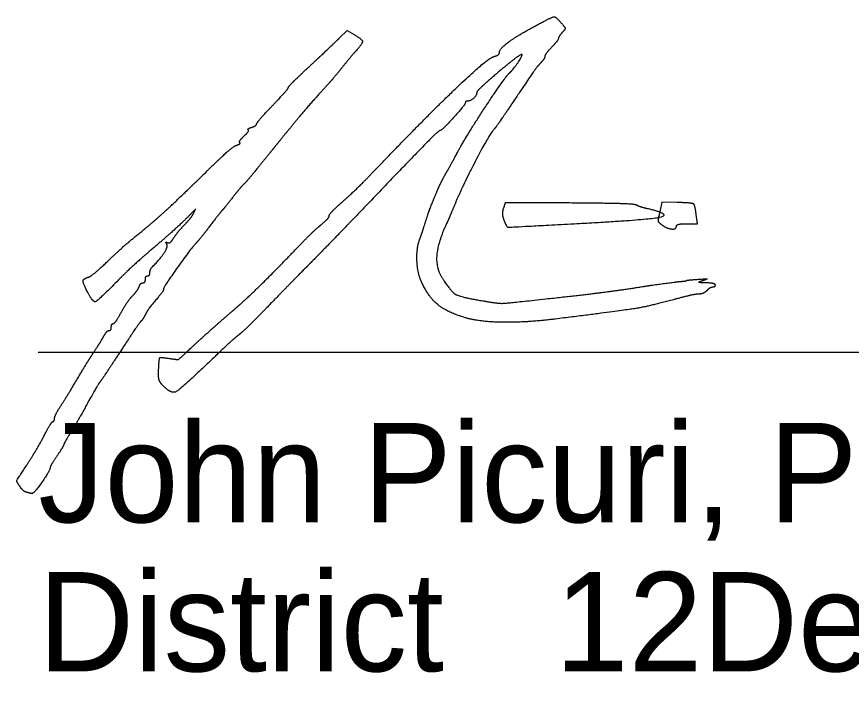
# Model space of a CAD drawing. Extents: x 0 to 81.5, y 0 to 35.2.
# Drawn here: x 24.497 to 25.674, y 8.063 to 9.028 of the extents above; entities that cross this region are included whole.
import ezdxf

# ---------------------------------------------------------------- set-up
doc = ezdxf.new("R2010")
doc.units = 0
doc.layers.add('SH_Data', color=7, linetype='Continuous')
doc.layers.add('SH_Text', color=7, linetype='Continuous')

msp = doc.modelspace()

# ---------------------------------------------------------------- linework, layer by layer
at = {"layer": 'SH_Data'}
msp.add_line((24.5279, 8.555), (28.0279, 8.555), dxfattribs=at)
msp.add_line((24.5279, 8.555), (28.0279, 8.555), dxfattribs=at)
at = {"layer": 'SH_Text'}
for p, q in [((25.1843, 8.7411), (25.1843, 8.7411)), ((25.4072, 8.7342), (25.4072, 8.7342)), ((24.7028, 8.5086), (24.7028, 8.5086)), ((24.5119, 8.3571), (24.5119, 8.3571))]:
    msp.add_line(p, q, dxfattribs=at)
for points in [[(24.9527, 8.9976), (24.9635, 9.0082), (24.9732, 9.0025)], [(24.7467, 8.7502), (24.7501, 8.7566), (24.7437, 8.7502)], [(25.277, 8.765), (25.1863, 8.7654), (25.1837, 8.7575)], [(25.4288, 8.7657), (25.407, 8.7662), (25.4041, 8.7525)], [(25.4425, 8.7358), (25.4573, 8.7358), (25.4556, 8.7489)]]:
    msp.add_lwpolyline(points, dxfattribs=at)
for points in [[(25.2302, 9.0154), (25.2528, 9.0275), (25.2579, 9.0276), (25.2676, 9.0159)], [(25.1781, 8.9771), (25.1781, 8.9823), (25.2041, 9.0014), (25.2302, 9.0154)], [(25.2676, 9.0159), (25.271, 9.0117), (25.2709, 9.0099), (25.2665, 9.0051)], [(24.9732, 9.0025), (24.9847, 8.9957), (24.9854, 8.9897), (24.9756, 8.979)], [(25.2665, 9.0051), (25.2636, 9.0019), (25.2613, 8.9982), (25.2613, 8.997)], [(24.9112, 8.9584), (24.9281, 8.9741), (24.9468, 8.9918), (24.9527, 8.9976)], [(25.2613, 8.997), (25.2613, 8.9957), (25.257, 8.99), (25.2517, 8.9844)], [(24.9756, 8.979), (24.9716, 8.9746), (24.9626, 8.9638), (24.9556, 8.9551)], [(25.2517, 8.9844), (25.2464, 8.9788), (25.2421, 8.973), (25.2421, 8.9716)], [(24.9988, 8.8073), (25.0691, 8.8809), (25.1611, 8.969), (25.1699, 8.9712)], [(25.2101, 8.974), (25.2101, 8.9762), (25.185, 8.9568), (25.1615, 8.9364)], [(25.1699, 8.9712), (25.1744, 8.9724), (25.1781, 8.975), (25.1781, 8.9771)], [(25.1926, 8.9486), (25.1972, 8.9526), (25.2101, 8.9713), (25.2101, 8.974)], [(25.2421, 8.9716), (25.2421, 8.9701), (25.2403, 8.9669), (25.2381, 8.9645)], [(24.8805, 8.9277), (24.8805, 8.9289), (24.8943, 8.9427), (24.9112, 8.9584)], [(25.2381, 8.9645), (25.23, 8.9554), (25.2268, 8.951), (25.2004, 8.9118)], [(24.9556, 8.9551), (24.9486, 8.9464), (24.9407, 8.9369), (24.9381, 8.9341)], [(25.1188, 8.836), (25.1307, 8.8584), (25.1861, 8.9428), (25.1926, 8.9486)], [(24.9381, 8.9341), (24.9267, 8.922), (24.8959, 8.8867), (24.8852, 8.8734)], [(25.1615, 8.9364), (25.1531, 8.929), (25.1461, 8.9218), (25.1461, 8.9204)], [(24.8581, 8.9022), (24.8704, 8.9151), (24.8805, 8.9266), (24.8805, 8.9277)], [(25.1461, 8.9204), (25.146, 8.9166), (25.1375, 8.9086), (25.1335, 8.9086)], [(25.1335, 8.9086), (25.1316, 8.9086), (25.13, 8.9075), (25.13, 8.9062)], [(25.2004, 8.9118), (25.1855, 8.8898), (25.1727, 8.8711), (25.1717, 8.8702)], [(24.8357, 8.8763), (24.8357, 8.8776), (24.8457, 8.8893), (24.8581, 8.9022)], [(25.13, 8.9062), (25.1298, 8.9033), (25.0968, 8.867), (25.0943, 8.867)], [(24.829, 8.8717), (24.8327, 8.8729), (24.8357, 8.8749), (24.8357, 8.8763)], [(24.8852, 8.8734), (24.8787, 8.8655), (24.8688, 8.8532), (24.863, 8.8462)], [(24.8179, 8.8591), (24.8222, 8.8631), (24.8249, 8.8671), (24.824, 8.868)], [(24.824, 8.868), (24.8231, 8.8689), (24.8254, 8.8706), (24.829, 8.8717)], [(25.0943, 8.867), (25.0923, 8.867), (25.0616, 8.8358), (24.9919, 8.7632)], [(25.1717, 8.8702), (25.1649, 8.8637), (25.1253, 8.7878), (25.1125, 8.7566)], [(24.8073, 8.8463), (24.8108, 8.8475), (24.8129, 8.8492), (24.812, 8.8502)], [(24.812, 8.8502), (24.811, 8.8511), (24.8137, 8.8552), (24.8179, 8.8591)], [(24.7708, 8.8148), (24.7873, 8.831), (24.8038, 8.8452), (24.8073, 8.8463)], [(24.863, 8.8462), (24.8573, 8.8391), (24.8456, 8.8247), (24.8371, 8.8142)], [(25.1042, 8.8094), (25.1058, 8.812), (25.1124, 8.824), (25.1188, 8.836)], [(24.6782, 8.7287), (24.6956, 8.7429), (24.7296, 8.7745), (24.7708, 8.8148)], [(24.8371, 8.8142), (24.8286, 8.8036), (24.82, 8.7935), (24.818, 8.7918)], [(24.958, 8.7678), (24.9689, 8.7775), (24.9873, 8.7952), (24.9988, 8.8073)], [(25.0741, 8.739), (25.079, 8.7553), (25.0974, 8.7984), (25.1042, 8.8094)], [(24.818, 8.7918), (24.816, 8.79), (24.8087, 8.7814), (24.8018, 8.7726)], [(24.8018, 8.7726), (24.7949, 8.7638), (24.7885, 8.7559), (24.7875, 8.755)], [(24.9381, 8.747), (24.9381, 8.7488), (24.947, 8.7582), (24.958, 8.7678)], [(24.9919, 8.7632), (24.9667, 8.7368), (24.9309, 8.7), (24.9125, 8.6813)], [(25.1125, 8.7566), (25.1096, 8.7495), (25.1059, 8.7409), (25.1042, 8.7374)], [(25.1837, 8.7575), (25.1822, 8.7529), (25.1824, 8.746), (25.1843, 8.7411)], [(25.3713, 8.7621), (25.3693, 8.7634), (25.3269, 8.7647), (25.277, 8.765)], [(25.2837, 8.7358), (25.3852, 8.7412), (25.4222, 8.7486), (25.3884, 8.7566)], [(25.3884, 8.7566), (25.381, 8.7583), (25.3732, 8.7608), (25.3713, 8.7621)], [(25.4522, 8.7635), (25.4513, 8.7644), (25.4408, 8.7654), (25.4288, 8.7657)], [(25.4556, 8.7489), (25.4546, 8.756), (25.4531, 8.7626), (25.4522, 8.7635)], [(24.7437, 8.7502), (24.7319, 8.7382), (24.7093, 8.7179), (24.6853, 8.6974)], [(24.734, 8.7342), (24.7392, 8.7395), (24.7449, 8.7467), (24.7467, 8.7502)], [(24.7875, 8.755), (24.7866, 8.7541), (24.779, 8.7445), (24.7707, 8.7336)], [(24.9264, 8.7342), (24.9328, 8.7394), (24.9381, 8.7452), (24.9381, 8.747)], [(25.4041, 8.7525), (25.4015, 8.7407), (25.402, 8.7382), (25.4072, 8.7342)], [(24.719, 8.7158), (24.7221, 8.7206), (24.7289, 8.7289), (24.734, 8.7342)], [(24.7707, 8.7336), (24.7624, 8.7227), (24.7537, 8.7119), (24.7514, 8.7096)], [(24.8968, 8.7058), (24.9066, 8.7161), (24.92, 8.7289), (24.9264, 8.7342)], [(25.0658, 8.714), (25.0674, 8.7181), (25.0711, 8.7293), (25.0741, 8.739)], [(25.1042, 8.7374), (25.0914, 8.7099), (25.0882, 8.6739), (25.0972, 8.6597)], [(25.1843, 8.7411), (25.1881, 8.731), (25.1912, 8.7308), (25.2837, 8.7358)], [(25.4072, 8.7342), (25.4142, 8.7289), (25.4277, 8.7278), (25.4277, 8.7326)], [(25.4277, 8.7326), (25.4277, 8.7343), (25.4343, 8.7358), (25.4425, 8.7358)], [(24.6251, 8.6822), (24.6465, 8.7025), (24.6521, 8.7074), (24.6782, 8.7287)], [(24.7514, 8.7096), (24.7447, 8.7029), (24.7045, 8.6465), (24.7045, 8.6438)], [(24.709, 8.7073), (24.7076, 8.7096), (24.708, 8.7103), (24.71, 8.7091)], [(24.71, 8.7091), (24.7119, 8.708), (24.7159, 8.711), (24.719, 8.7158)], [(25.0676, 8.6554), (25.0623, 8.6674), (25.0613, 8.7027), (25.0658, 8.714)], [(24.6853, 8.6974), (24.6721, 8.6862), (24.6532, 8.6689), (24.6434, 8.6589)], [(24.6894, 8.6756), (24.701, 8.6875), (24.7112, 8.7039), (24.709, 8.7073)], [(24.8125, 8.6222), (24.8252, 8.6333), (24.8708, 8.6785), (24.8968, 8.7058)], [(24.5983, 8.6604), (24.6015, 8.6614), (24.6136, 8.6712), (24.6251, 8.6822)], [(24.6853, 8.6668), (24.6853, 8.6693), (24.6871, 8.6732), (24.6894, 8.6756)], [(24.9125, 8.6813), (24.894, 8.6626), (24.8656, 8.6335), (24.8493, 8.6167)], [(24.6789, 8.6574), (24.6789, 8.66), (24.6803, 8.6622), (24.6821, 8.6622)], [(24.6821, 8.6622), (24.6838, 8.6622), (24.6853, 8.6642), (24.6853, 8.6668)], [(24.5973, 8.6396), (24.5909, 8.6521), (24.5912, 8.6582), (24.5983, 8.6604)], [(24.6434, 8.6589), (24.6123, 8.6275), (24.6051, 8.6245), (24.5973, 8.6396)], [(24.6703, 8.6474), (24.6714, 8.6503), (24.6737, 8.6526), (24.6756, 8.6526)], [(24.6756, 8.6526), (24.6774, 8.6526), (24.6789, 8.6547), (24.6789, 8.6574)], [(25.1298, 8.6033), (25.1041, 8.6109), (25.0771, 8.6335), (25.0676, 8.6554)], [(25.0972, 8.6597), (25.11, 8.6397), (25.1233, 8.6323), (25.1559, 8.6269)], [(25.3813, 8.6474), (25.3941, 8.6494), (25.4241, 8.6535), (25.4341, 8.6545)], [(25.4341, 8.6545), (25.4385, 8.6549), (25.4421, 8.6555), (25.4421, 8.6558)], [(25.4421, 8.6558), (25.4421, 8.6561), (25.4493, 8.6568), (25.4581, 8.6575)], [(25.4581, 8.6575), (25.4698, 8.6583), (25.4719, 8.6579), (25.4661, 8.6559)], [(25.4661, 8.6559), (25.4588, 8.6535), (25.4592, 8.6532), (25.4701, 8.6529)], [(25.4701, 8.6529), (25.4767, 8.6527), (25.4821, 8.6511), (25.4821, 8.6494)], [(25.4821, 8.6494), (25.4821, 8.6476), (25.4805, 8.6462), (25.4786, 8.6462)], [(24.6607, 8.634), (24.6649, 8.6386), (24.6692, 8.6446), (24.6703, 8.6474)], [(24.7045, 8.6438), (24.7045, 8.6417), (24.7011, 8.6372), (24.6858, 8.6188)], [(25.2437, 8.6299), (25.2997, 8.636), (25.3497, 8.6424), (25.3813, 8.6474)], [(25.4704, 8.6414), (25.4678, 8.6387), (25.4625, 8.6366), (25.4586, 8.6365)], [(25.4786, 8.6462), (25.4767, 8.6462), (25.473, 8.644), (25.4704, 8.6414)], [(24.6446, 8.6104), (24.6492, 8.6188), (24.6564, 8.6295), (24.6607, 8.634)], [(25.1559, 8.6269), (25.1766, 8.6234), (25.188, 8.6238), (25.2437, 8.6299)], [(25.4277, 8.6299), (25.39, 8.6196), (25.3508, 8.6131), (25.2565, 8.6014)], [(25.4586, 8.6365), (25.4548, 8.6365), (25.4409, 8.6335), (25.4277, 8.6299)], [(24.6858, 8.6188), (24.6842, 8.6169), (24.6811, 8.6119), (24.6788, 8.6076)], [(24.7826, 8.5962), (24.793, 8.6052), (24.8065, 8.6169), (24.8125, 8.6222)], [(24.8493, 8.6167), (24.833, 8.5999), (24.8153, 8.5828), (24.81, 8.5786)], [(24.6336, 8.595), (24.635, 8.595), (24.64, 8.6019), (24.6446, 8.6104)], [(24.6788, 8.6076), (24.6766, 8.6033), (24.6737, 8.5991), (24.6726, 8.5982)], [(25.2565, 8.6014), (25.2157, 8.5964), (25.1501, 8.5974), (25.1298, 8.6033)], [(24.6309, 8.5902), (24.6309, 8.5928), (24.6321, 8.595), (24.6336, 8.595)], [(24.6726, 8.5982), (24.6714, 8.5973), (24.6586, 8.5786), (24.6442, 8.5566)], [(24.7445, 8.5619), (24.755, 8.5717), (24.7722, 8.5871), (24.7826, 8.5962)], [(24.6206, 8.5778), (24.6229, 8.582), (24.6262, 8.5854), (24.6278, 8.5854)], [(24.6278, 8.5854), (24.6295, 8.5854), (24.6309, 8.5875), (24.6309, 8.5902)], [(24.6082, 8.5578), (24.6128, 8.5647), (24.6183, 8.5737), (24.6206, 8.5778)], [(24.81, 8.5786), (24.8046, 8.5744), (24.7898, 8.561), (24.7771, 8.5488)], [(24.5762, 8.5057), (24.5933, 8.5344), (24.601, 8.5469), (24.6082, 8.5578)], [(24.6442, 8.5566), (24.6297, 8.5346), (24.6167, 8.5151), (24.6152, 8.5132)], [(24.7137, 8.5458), (24.7244, 8.5441), (24.7268, 8.5453), (24.7445, 8.5619)], [(24.6975, 8.5281), (24.6982, 8.5459), (24.7002, 8.548), (24.7137, 8.5458)], [(24.7771, 8.5488), (24.7295, 8.5031), (24.715, 8.4952), (24.7028, 8.5086)], [(24.7028, 8.5086), (24.699, 8.5129), (24.6972, 8.5194), (24.6975, 8.5281)], [(24.6152, 8.5132), (24.6127, 8.51), (24.6084, 8.5026), (24.5872, 8.4646)], [(24.5613, 8.4818), (24.567, 8.4907), (24.5737, 8.5014), (24.5762, 8.5057)], [(24.5509, 8.4617), (24.5509, 8.4638), (24.5555, 8.4728), (24.5613, 8.4818)], [(24.5483, 8.4569), (24.5497, 8.4574), (24.5509, 8.4596), (24.5509, 8.4617)], [(24.5872, 8.4646), (24.5825, 8.4562), (24.5753, 8.444), (24.5712, 8.4375)], [(24.5359, 8.4366), (24.5413, 8.4471), (24.5469, 8.4563), (24.5483, 8.4569)], [(24.5114, 8.3953), (24.5194, 8.4075), (24.5304, 8.426), (24.5359, 8.4366)], [(24.5712, 8.4375), (24.567, 8.4309), (24.5637, 8.4248), (24.5637, 8.424)], [(24.5637, 8.424), (24.5637, 8.4232), (24.5593, 8.4161), (24.5541, 8.4083)], [(24.5541, 8.4083), (24.5488, 8.4005), (24.5445, 8.3929), (24.5445, 8.3916)], [(24.5017, 8.3659), (24.4972, 8.3728), (24.4978, 8.3746), (24.5114, 8.3953)], [(24.5445, 8.3916), (24.5445, 8.3879), (24.5214, 8.3549), (24.5191, 8.3554)], [(24.5119, 8.3571), (24.509, 8.3579), (24.5044, 8.3619), (24.5017, 8.3659)], [(24.5191, 8.3554), (24.5181, 8.3556), (24.5149, 8.3564), (24.5119, 8.3571)]]:
    msp.add_open_spline(points, degree=2, dxfattribs=at)

# ---------------------------------------------------------------- texts
for s, p in [('John Picuri, P.E., S.I.', (24.5279, 8.315)), ('District       Deputy Director', (24.5279, 8.105)), ('District       Deputy Director', (24.5279, 8.105)), ('              12', (24.5279, 8.105))]:
    msp.add_text(s, height=0.14, dxfattribs=at).set_placement(p)

doc.saveas('drawing.dxf')
